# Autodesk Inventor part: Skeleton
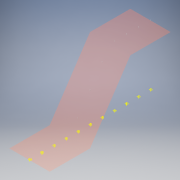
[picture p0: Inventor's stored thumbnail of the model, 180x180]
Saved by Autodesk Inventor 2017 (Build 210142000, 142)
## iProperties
Part Number: Skeleton
Material: Všeobecné
Document SubType Name: Modeling
Designer: Polesny
Mass: 0.00863938 g
Surface Area: 0.518363 cm^2
Volume: 0.00863938 cm^3
Density: 1 g/cm^3
Appearance: Výchozí
Mass: 0
Author: Polesny
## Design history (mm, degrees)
sketch "Krivka"
  geometry: L1 (0, 0)-(0, -100); L2 (0, -100)-(150, -200); L3 (150, -200)-(150, -300)
  constraints: 6 end point, 1 parallel, 1 vertical
  dimensions: "d0" = 100 distance of L1.start L1.end; "d1" = 100 distance of L2.end L3.end; "d2" = 100 vertical distance of L1.end L2.end; "d3" = 150 distance between parallel lines of L1 L3
sketch "Náčrt2"
  geometry: L1 (0, 0)-(0, -300)
  constraints: 2 end point, 1 vertical
pattern_linear "Obdélníkové pole1" sketch "Náčrt2"
feature "VysunutíDoPlochy1" dims "d6" = 100, "d7" = 0
sketch "3D náčrt1"
  node "Promítnout na plochu1"
sketch "Náčrt3"
  geometry: C1 r 0.5 at (0, 0); 1 further point
  constraints: 1 centre point, 1 coincident
  dimensions: "d8" = 1 diameter of C1
extrude "Vysunutí1" new body sketch "Náčrt3" distance "d9" = 1; taper "d10" = 0 deg
feature "Pole řízené náčrtem1"
node "Těleso1"
node "Pracovní bod1"
node "Pracovní bod2"
node "Pracovní bod3"
node "Pracovní bod4"
node "Pracovní bod5"
node "Pracovní bod6"
node "Pracovní bod7"
node "Pracovní bod8"
node "Pracovní bod9"
node "Pracovní bod10"
node "Povrch1"
